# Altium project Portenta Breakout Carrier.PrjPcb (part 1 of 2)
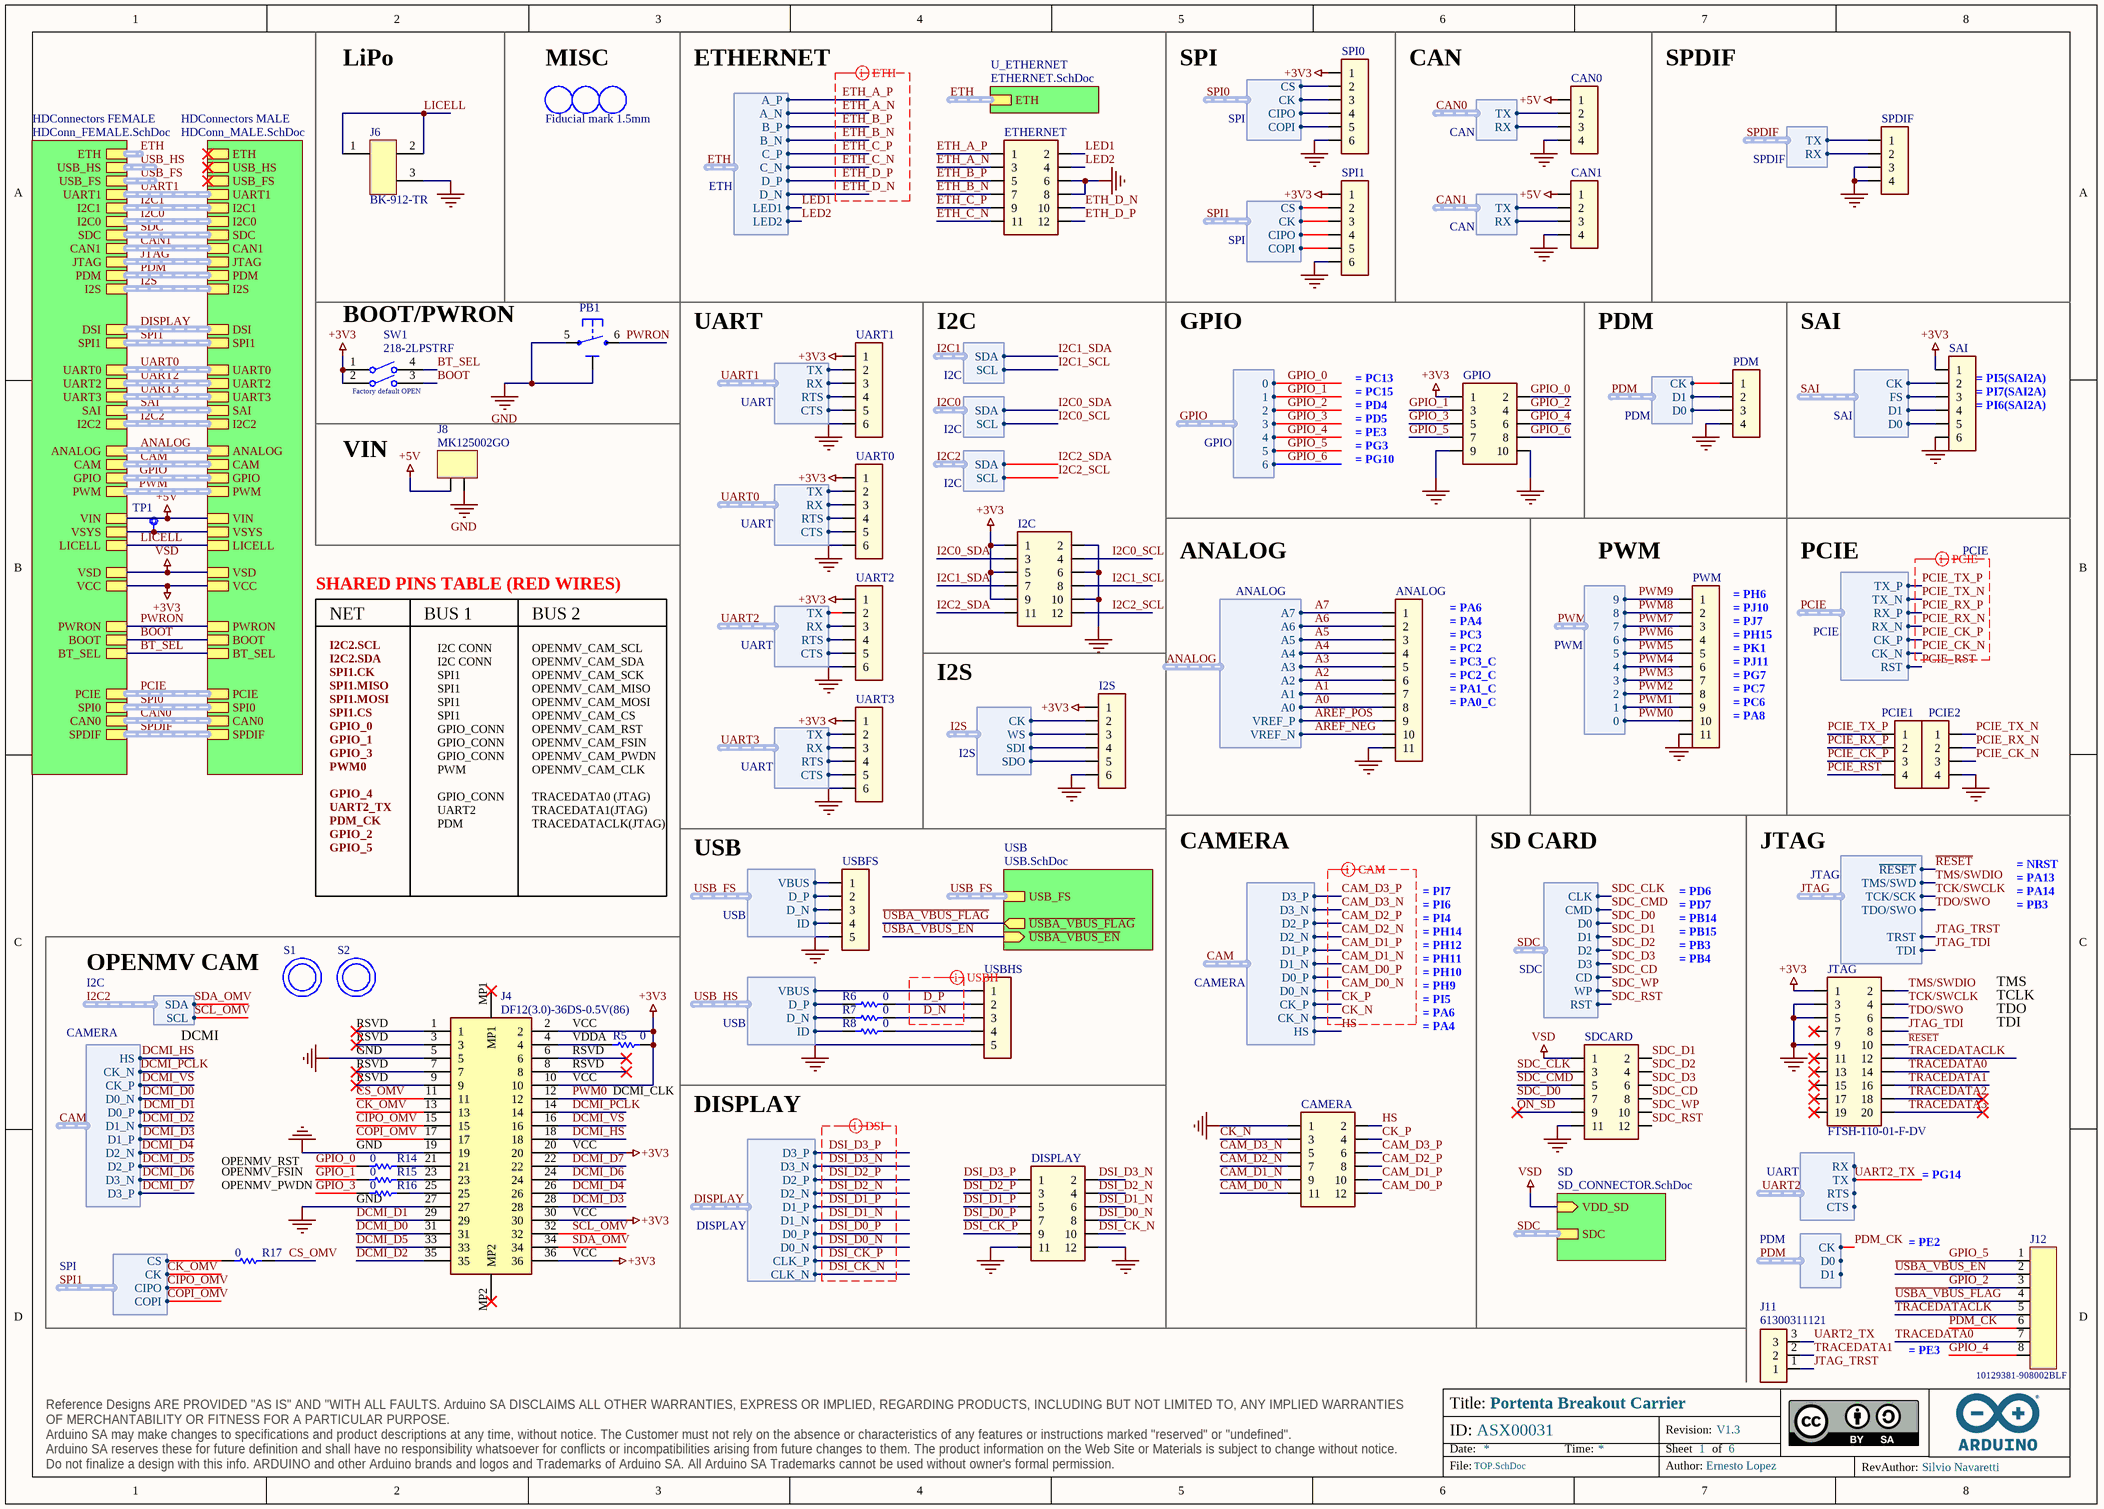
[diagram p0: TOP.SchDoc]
THICKNESS: 1.6mm; THD: X; TBD: _; TABS: _; SOLDERMASK_TOP: X; SOLDERMASK_PEELABLE_TOP: _; SOLDERMASK_PEELABLE_COLOR: _; SOLDERMASK_PEELABLE_BOTTOM: _; SOLDERMASK_COLOR: BLACK; SOLDERMASK_BOTTOM: X; SN/PB: _; SMD: X; SKU: ASX00031; SILK_TOP: X; SILK_COLOR: WHITE; SILK_BOTTOM: _; SCORING: X; RIGID/FLEX: _; RIGID: X; Revision: V1.3; PRESSFIT: _; POLYMIDE: _; PCB_SIZE: 164.00 mm x 72.00 mm; PANEL_SIZE: 184.00 mm x 165.00 mm; PANEL_REQUESTED: _; PANEL_PROVIDED: X; PANEL_NO: _; N_FIGURES: 2; NLAYERS: 4; NI/AU: _; MIN_TRACK_WIDTH_OUTER: 0.15mm; MIN_TRACK_WIDTH_INNER: 0.15mm; MIN_INSULATION_OUTER: 0.15mm; MIN_INSULATION_INNER: 0.15mm; MILLING: X; IPCNA: X; IPC3: _; IPC2: _; IPC1: _; HOLE_TOP_BOTTOM: X; HAL_LF: _; HAL: _; FR4_HTG: _; FR4: X; FLEX: _; FINISH_TBD: _; ENIG: X; EDGE_PLATING: _; DRILLS_SOLDER_FILLING: X; DRILLS_SLOT: _; DRILLS_RESIN_FILLING: _; DRILLS_PRESSFIT: _; DRILLS_LASER: _; DRILLS_FULL: X; DRILLS_COPPER_FILLING: _; DRILLS_BURIED: _; DRILLS_BLIND: _; BGA: _; Author: Ernesto Lopez; ADJUSTMENTS: _
6 sheets, 71 parts. Net scope: hierarchical (ports join the sheet entries above them; power ports are global).
Board files: Portenta_Brkout_Carrier.PcbDoc, Portenta_Carrier_Panel.PcbDoc
Sheets:
  TOP.SchDoc
    HDConnectors FEMALE = HDConn_FEMALE.SchDoc
    U_ETHERNET = ETHERNET.SchDoc
    USB = USB.SchDoc
    SD = SD_CONNECTOR.SchDoc
    HDConnectors MALE = HDConn_MALE.SchDoc

## Sheet TOP.SchDoc: Portenta Breakout Carrier
size A3; Author: Ernesto Lopez; DocumentNumber: ASX00031; Revision: V1.3; SheetNumber: 1; SheetTotal: 6; RevAuthor: Silvio Navaretti

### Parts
ANALOG  PIN HEADER 2.54mm VERT. 1x11POS  [PIN HEADER 2.54mm VERT. 1x11POS]  (value not drawn)
CAMERA  PIN HEADER 2.54mm VERT. 2x6POS  [PIN HEADER 2.54mm VERT. 2x6POS]  (value not drawn)
CAN0  PIN HEADER 2.54mm VERT. 1x4POS  [PIN HEADER 2.54mm VERT. 1x4POS-Footprint-1]  (value not drawn)
CAN1  PIN HEADER 2.54mm VERT. 1x4POS  [PIN HEADER 2.54mm VERT. 1x4POS-Footprint-1]  (value not drawn)
DISPLAY  PIN HEADER 2.54mm VERT. 2x6POS  [PIN HEADER 2.54mm VERT. 2x6POS]  (value not drawn)
ETHERNET  PIN HEADER 2.54mm VERT. 2x6POS  [PIN HEADER 2.54mm VERT. 2x6POS]  (value not drawn)
FD1  Fiducial mark 1.5mm  [FIDUCIAL-1.5]  (no BOM)
FD2  Fiducial mark 1.5mm  [FIDUCIAL-1.5]  (value not drawn)  (no BOM)
FD3  Fiducial mark 1.5mm  [FIDUCIAL-1.5]  (value not drawn)  (no BOM)
GPIO  PIN HEADER 2.54mm VERT. 2x5POS  [PIN HEADER 2.54mm VERT. 2x5POS]  (value not drawn)
I2C  PIN HEADER 2.54mm VERT. 2x6POS  [PIN HEADER 2.54mm VERT. 2x6POS]  (value not drawn)
I2S  PIN HEADER 2.54mm VERT. 1x6POS  [PIN HEADER 2.54mm VERT. 1x6POS]  (value not drawn)
J4  DF12(3.0)-36DS-0.5V(86)  [DF12(3.0)-36DS-0.5V(86)-Footprint-1]
J6  BK-912-TR  [MPD-CN-DIN-3_V]
J8  MK125002GO  [MK125002GO]
J11  61300311121  [61300311121]
J12  10129381-908002BLF  [61300211121]
JTAG  FTSH-110-01-F-DV  [FTSH-105-01-F-DV-Footprint-1]
PB1  PTS820J25KSMTRLFS  [C&K_PTS820_NO_HOLES-1]  (value not drawn)
PCIE1  PIN HEADER 2.54mm VERT. 1x4POS  [PIN HEADER 2.54mm VERT. 1x4POS-Footprint-1]  (value not drawn)
PCIE2  PIN HEADER 2.54mm VERT. 1x4POS  [PIN HEADER 2.54mm VERT. 1x4POS-Footprint-1]  (value not drawn)
PDM  PIN HEADER 2.54mm VERT. 1x4POS  [PIN HEADER 2.54mm VERT. 1x4POS-Footprint-1]  (value not drawn)
PWM  PIN HEADER 2.54mm VERT. 1x11POS  [PIN HEADER 2.54mm VERT. 1x11POS]  (value not drawn)
R5  value 0  [RES-0402]  (hidden comment: CRCW04020000Z0EDC)
R6  value 0  [RES-0402]  (hidden comment: CRCW04020000Z0EDC)
R7  value 0  [RES-0402]  (hidden comment: CRCW04020000Z0EDC)
R8  value 0  [RES-0402]  (hidden comment: CRCW04020000Z0EDC)
R14  value 0  [RES-0402]  (hidden comment: CRCW04020000Z0EDC)
R15  value 0  [RES-0402]  (hidden comment: CRCW04020000Z0EDC)
R16  value 0  [RES-0402]  (hidden comment: CRCW04020000Z0EDC)
R17  value 0  [RES-0402]  (hidden comment: CRCW04020000Z0EDC)
S1  9774030243R  [9774030243R-Footprint-1]  (value not drawn)
S2  9774030243R  [9774030243R-Footprint-1]  (value not drawn)
SAI  PIN HEADER 2.54mm VERT. 1x6POS  [PIN HEADER 2.54mm VERT. 1x6POS]  (value not drawn)
SDCARD  PIN HEADER 2.54mm VERT. 2x6POS  [PIN HEADER 2.54mm VERT. 2x6POS]  (value not drawn)
SPDIF  PIN HEADER 2.54mm VERT. 1x4POS  [PIN HEADER 2.54mm VERT. 1x4POS-Footprint-1]  (value not drawn)
SPI0  PIN HEADER 2.54mm VERT. 1x6POS  [PIN HEADER 2.54mm VERT. 1x6POS]  (value not drawn)
SPI1  PIN HEADER 2.54mm VERT. 1x6POS  [PIN HEADER 2.54mm VERT. 1x6POS]  (value not drawn)
SW1  218-2LPSTRF  [CTS-218-2LPST_V]
TP1  CMP-018-0006-A.4  [TP-1.27MM]  (value not drawn)  (no BOM)
UART0  PIN HEADER 2.54mm VERT. 1x6POS  [PIN HEADER 2.54mm VERT. 1x6POS]  (value not drawn)
UART1  PIN HEADER 2.54mm VERT. 1x6POS  [PIN HEADER 2.54mm VERT. 1x6POS]  (value not drawn)
UART2  PIN HEADER 2.54mm VERT. 1x6POS  [PIN HEADER 2.54mm VERT. 1x6POS]  (value not drawn)
UART3  PIN HEADER 2.54mm VERT. 1x6POS  [PIN HEADER 2.54mm VERT. 1x6POS]  (value not drawn)
USBFS  PIN HEADER 2.54mm VERT. 1x5POS  [PIN HEADER 2.54mm VERT. 1x5POS]  (value not drawn)
USBHS  PIN HEADER 2.54mm VERT. 1x5POS  [PIN HEADER 2.54mm VERT. 1x5POS]  (value not drawn)

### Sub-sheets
HDConnectors FEMALE = HDConn_FEMALE.SchDoc: PWRON, BOOT, USB_HS (harness USB), UART0 (harness UART), SAI (harness SAI), I2C2 (harness I2C), USB_FS (harness USB), JTAG (harness JTAG), BT_SEL, I2S (harness I2S), I2C0 (harness I2C), ETH (harness ETH), PWM (harness PWM), I2C1 (harness I2C), GPIO (harness GPIO), SPI1 (harness SPI), VCC, UART3 (harness UART), CAM (harness CAMERA), LICELL, PDM (harness PDM), DSI (harness DISPLAY), CAN1 (harness CAN), SDC (harness SDC), UART2 (harness UART), ANALOG (harness ANALOG), UART1 (harness UART), VIN, VSYS, CAN0 (harness GPIO), SPI0 (harness GPIO), PCIE (harness GPIO), SPDIF (harness GPIO), VSD
HDConnectors MALE = HDConn_MALE.SchDoc: SPI1 (harness SPI), SAI (harness SAI), UART3 (harness UART), UART2 (harness UART), I2C2 (harness I2C), UART1 (harness UART), VSD, I2C0 (harness I2C), VIN, USB_HS (harness USB), PCIE (harness PCIE), I2C1 (harness I2C), CAM (harness CAMERA), VSYS, I2S (harness I2S), SPDIF (harness SPDIF), BOOT, CAN1 (harness CAN), ANALOG (harness ANALOG), PWRON, VCC, SPI0 (harness SPI), PWM (harness PWM), UART0 (harness UART), USB_FS (harness USB), SDC (harness SDC), PDM (harness PDM), ETH (harness ETH), DSI (harness DISPLAY), CAN0 (harness CAN), BT_SEL, LICELL, JTAG (harness JTAG), GPIO (harness GPIO)
SD = SD_CONNECTOR.SchDoc: SDC (harness SDC), VDD_SD (in)
U_ETHERNET = ETHERNET.SchDoc: ETH (harness ETH)
USB = USB.SchDoc: USB_FS (harness ETH), ~{USBA_VBUS_FLAG} (out), ~{USBA_VBUS_EN} (in)

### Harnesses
UART: RX, TX, RTS, CTS
I2C: SCL, SDA
I2S: CK, SDI, SDO, WS
USB: VBUS, D_P, D_N, ID
ETH: A_P, A_N, B_P, B_N, C_P, C_N, D_P, D_N, LED1, LED2
DISPLAY: CLK_N, CLK_P, D0_N, D0_P, D1_N, D1_P, D2_N, D2_P, D3_N, D3_P
CAN: RX, TX
SPI: CS, CK, CIPO, COPI
GPIO: 0, 1, 2, 3, 4, 5, 6
ANALOG: VREF_P, A0, A1, A2, A3, A7, A6, A5, A4, VREF_N
SDC: CLK, CMD, D0, D1, D2, D3, CD, WP, RST
PDM: CK, D0, D1
JTAG: ~{RESET}, TCK/SCK, TDI, TDO/SWO, TMS/SWD, TRST
SAI: CK, FS, D0, D1
PWM: 0, 1, 2, 3, 4, 5, 6, 7, 8, 9
PCIE: TX_P, TX_N, RX_P, RX_N, CK_P, CK_N, RST
SPDIF: RX, TX
CAMERA: D3_P, D3_N, D2_P, D2_N, D1_P, D1_N, D0_P, D0_N, CK_P, CK_N, HS
I2C: SDA, SCL

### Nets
+3V3: GPIO.1 I2C.1 I2C.5 I2C.9 I2S.1 J4.2 J4.10 J4.20 J4.30 J4.36 JTAG.1 R5.1 SAI.1 SPI0.1 SPI1.1 SW1.1 SW1.2 UART0.1 UART1.1 UART2.1 UART3.1 ; sheet HDConnectors FEMALE/VCC, sheet HDConnectors MALE/VCC
+5V: CAN0.1 CAN1.1 J8.1 ; sheet HDConnectors FEMALE/VIN, sheet HDConnectors MALE/VIN
GND: ANALOG.11 CAMERA.1 CAN0.4 CAN1.4 DISPLAY.11 DISPLAY.12 ETHERNET.6 ETHERNET.8 GPIO.9 GPIO.10 I2C.2 I2C.6 I2C.10 I2S.6 J4.5 J4.19 J4.27 J6.3(NEGATIVE) J8.2 JTAG.3 JTAG.5 JTAG.9 PB1.5 PB1.PAD PCIE2.4 PDM.4 PWM.11 SAI.6 SDCARD.11 SPDIF.3 SPDIF.4 SPI0.6 SPI1.6 UART0.6 UART1.6 UART2.6 UART3.6 USBFS.5 USBHS.5
VSD: SDCARD.1 ; sheet HDConnectors FEMALE/VSD, sheet SD/VDD_SD, sheet HDConnectors MALE/VSD
A0: ANALOG.8 ; sheet HDConnectors FEMALE/ANALOG.A0
A1: ANALOG.7 ; sheet HDConnectors FEMALE/ANALOG.A1
A2: ANALOG.6 ; sheet HDConnectors FEMALE/ANALOG.A2
A3: ANALOG.5 ; sheet HDConnectors FEMALE/ANALOG.A3
A4: ANALOG.4 ; sheet HDConnectors FEMALE/ANALOG.A4
A5: ANALOG.3 ; sheet HDConnectors FEMALE/ANALOG.A5
A6: ANALOG.2 ; sheet HDConnectors FEMALE/ANALOG.A6
A7: ANALOG.1 ; sheet HDConnectors FEMALE/ANALOG.A7
AREF_NEG: ANALOG.10 ; sheet HDConnectors FEMALE/ANALOG.VREF_N  [project net ANALOG.VREF_N]
AREF_POS: ANALOG.9 ; sheet HDConnectors FEMALE/ANALOG.VREF_P  [project net ANALOG.VREF_P]
BOOT: SW1.3 ; sheet HDConnectors FEMALE/BOOT, sheet HDConnectors MALE/BOOT
BT_SEL: SW1.4 ; sheet HDConnectors FEMALE/BT_SEL, sheet HDConnectors MALE/BT_SEL
CAM_D0_N: CAMERA.11 J4.31 ; sheet HDConnectors FEMALE/CAM.D0_N  [also labelled DCMI_D0]  [project net CAM.D0_N]
CAM_D0_P: CAMERA.12 J4.29 ; sheet HDConnectors FEMALE/CAM.D0_P  [also labelled DCMI_D1]  [project net CAM.D0_P]
CAM_D1_N: CAMERA.9 J4.35 ; sheet HDConnectors FEMALE/CAM.D1_N  [also labelled DCMI_D2]  [project net CAM.D1_N]
CAM_D1_P: CAMERA.10 J4.28 ; sheet HDConnectors FEMALE/CAM.D1_P  [also labelled DCMI_D3]  [project net CAM.D1_P]
CAM_D2_N: CAMERA.7 J4.26 ; sheet HDConnectors FEMALE/CAM.D2_N  [also labelled DCMI_D4]  [project net CAM.D2_N]
CAM_D2_P: CAMERA.8 J4.33 ; sheet HDConnectors FEMALE/CAM.D2_P  [also labelled DCMI_D5]  [project net CAM.D2_P]
CAM_D3_N: CAMERA.5 J4.24 ; sheet HDConnectors FEMALE/CAM.D3_N  [also labelled DCMI_D6]  [project net CAM.D3_N]
CAM_D3_P: CAMERA.6 J4.22 ; sheet HDConnectors FEMALE/CAM.D3_P  [also labelled DCMI_D7]  [project net CAM.D3_P]
CAN0.RX: CAN0.3 ; sheet HDConnectors FEMALE/CAN0.RX
CAN0.TX: CAN0.2 ; sheet HDConnectors FEMALE/CAN0.TX
CAN1.RX: CAN1.3 ; sheet HDConnectors FEMALE/CAN1.RX
CAN1.TX: CAN1.2 ; sheet HDConnectors FEMALE/CAN1.TX
CIPO_OMV: J4.15 SPI1.4 ; sheet HDConnectors FEMALE/SPI1.CIPO
CK_N: CAMERA.3 J4.14 ; sheet HDConnectors FEMALE/CAM.CK_N  [also labelled DCMI_PCLK]  [project net CAM.CK_N]
CK_OMV: J4.13 SPI1.3 ; sheet HDConnectors FEMALE/SPI1.CK
CK_P: CAMERA.4 J4.16 ; sheet HDConnectors FEMALE/CAM.CK_P  [also labelled DCMI_VS]  [project net CAM.CK_P]
COPI_OMV: J4.17 SPI1.5 ; sheet HDConnectors FEMALE/SPI1.COPI
CS_OMV: J4.11 R17.1  [project net CS_OMV_1]
D_N: R7.1 USBHS.3  [project net D_N_1]
D_P: R6.1 USBHS.2  [project net D_P_1]
DCMI_HS: CAMERA.2 J4.18 ; sheet HDConnectors FEMALE/CAM.HS  [also labelled HS]  [project net CAM.HS]
DSI_CK_N: DISPLAY.10 ; sheet HDConnectors FEMALE/DSI.CLK_N  [project net DISPLAY.CLK_N]
DSI_CK_P: DISPLAY.9 ; sheet HDConnectors FEMALE/DSI.CLK_P  [project net DISPLAY.CLK_P]
DSI_D0_N: DISPLAY.8 ; sheet HDConnectors FEMALE/DSI.D0_N  [project net DISPLAY.D0_N]
DSI_D0_P: DISPLAY.7 ; sheet HDConnectors FEMALE/DSI.D0_P  [project net DISPLAY.D0_P]
DSI_D1_N: DISPLAY.6 ; sheet HDConnectors FEMALE/DSI.D1_N  [project net DISPLAY.D1_N]
DSI_D1_P: DISPLAY.5 ; sheet HDConnectors FEMALE/DSI.D1_P  [project net DISPLAY.D1_P]
DSI_D2_N: DISPLAY.4 ; sheet HDConnectors FEMALE/DSI.D2_N  [project net DISPLAY.D2_N]
DSI_D2_P: DISPLAY.3 ; sheet HDConnectors FEMALE/DSI.D2_P  [project net DISPLAY.D2_P]
DSI_D3_N: DISPLAY.2 ; sheet HDConnectors FEMALE/DSI.D3_N  [project net DISPLAY.D3_N]
DSI_D3_P: DISPLAY.1 ; sheet HDConnectors FEMALE/DSI.D3_P  [project net DISPLAY.D3_P]
ETH_A_N: ETHERNET.3 ; sheet HDConnectors FEMALE/ETH.A_N  [project net ETH.A_N]
ETH_A_P: ETHERNET.1 ; sheet HDConnectors FEMALE/ETH.A_P  [project net ETH.A_P]
ETH_B_N: ETHERNET.7 ; sheet HDConnectors FEMALE/ETH.B_N  [project net ETH.B_N]
ETH_B_P: ETHERNET.5 ; sheet HDConnectors FEMALE/ETH.B_P  [project net ETH.B_P]
ETH_C_N: ETHERNET.11 ; sheet HDConnectors FEMALE/ETH.C_N  [project net ETH.C_N]
ETH_C_P: ETHERNET.9 ; sheet HDConnectors FEMALE/ETH.C_P  [project net ETH.C_P]
ETH_D_N: ETHERNET.10 ; sheet HDConnectors FEMALE/ETH.D_N  [project net ETH.D_N]
ETH_D_P: ETHERNET.12 ; sheet HDConnectors FEMALE/ETH.D_P  [project net ETH.D_P]
GPIO_0: GPIO.2 R14.2 ; sheet HDConnectors FEMALE/GPIO.0  [project net GPIO.0]
GPIO_1: GPIO.3 R15.2 ; sheet HDConnectors FEMALE/GPIO.1  [project net GPIO.1]
GPIO_2: GPIO.4 J12.3 ; sheet HDConnectors FEMALE/GPIO.2  [project net GPIO.2]
GPIO_3: GPIO.5 R16.2 ; sheet HDConnectors FEMALE/GPIO.3  [project net GPIO.3]
GPIO_4: GPIO.6 J12.8 ; sheet HDConnectors FEMALE/GPIO.4  [project net GPIO.4]
GPIO_5: GPIO.7 J12.1 ; sheet HDConnectors FEMALE/GPIO.5  [project net GPIO.5]
GPIO_6: GPIO.8 ; sheet HDConnectors FEMALE/GPIO.6  [project net GPIO.6]
I2C0_SCL: I2C.4 ; sheet HDConnectors FEMALE/I2C0.SCL  [project net I2C0.SCL]
I2C0_SDA: I2C.3 ; sheet HDConnectors FEMALE/I2C0.SDA  [project net I2C0.SDA]
I2C1_SCL: I2C.8 ; sheet HDConnectors FEMALE/I2C1.SCL  [project net I2C1.SCL]
I2C1_SDA: I2C.7 ; sheet HDConnectors FEMALE/I2C1.SDA  [project net I2C1.SDA]
I2C2_SCL: I2C.12 J4.32 ; sheet HDConnectors FEMALE/I2C2.SCL  [also labelled SCL_OMV]  [project net I2C2.SCL]
I2C2_SDA: I2C.11 J4.34 ; sheet HDConnectors FEMALE/I2C2.SDA  [also labelled SDA_OMV]  [project net I2C2.SDA]
I2S.CK: I2S.2 ; sheet HDConnectors FEMALE/I2S.CK
I2S.SDI: I2S.4 ; sheet HDConnectors FEMALE/I2S.SDI
I2S.SDO: I2S.5 ; sheet HDConnectors FEMALE/I2S.SDO
I2S.WS: I2S.3 ; sheet HDConnectors FEMALE/I2S.WS
JTAG_TDI: JTAG.8 ; sheet HDConnectors FEMALE/JTAG.TDI  [project net JTAG.TDI]
JTAG_TRST: J11.1 ; sheet HDConnectors FEMALE/JTAG.TRST  [project net JTAG.TRST]
LED1: ETHERNET.2 ; sheet HDConnectors FEMALE/ETH.LED1  [project net ETH.LED1]
LED2: ETHERNET.4 ; sheet HDConnectors FEMALE/ETH.LED2  [project net ETH.LED2]
LICELL: J6.1(POSITIVE) J6.2(POSITIVE) ; sheet HDConnectors FEMALE/LICELL, sheet HDConnectors MALE/LICELL
ON_SD: SDCARD.9  [project net ON_SD_1]
PCIE_CK_N: PCIE2.3 ; sheet HDConnectors FEMALE/PCIE.CK_N  [project net PCIE.CK_N]
PCIE_CK_P: PCIE1.3 ; sheet HDConnectors FEMALE/PCIE.CK_P  [project net PCIE.CK_P]
PCIE_RST: PCIE1.4 ; sheet HDConnectors FEMALE/PCIE.RST  [project net PCIE.RST]
PCIE_RX_N: PCIE2.2 ; sheet HDConnectors FEMALE/PCIE.RX_N  [project net PCIE.RX_N]
PCIE_RX_P: PCIE1.2 ; sheet HDConnectors FEMALE/PCIE.RX_P  [project net PCIE.RX_P]
PCIE_TX_N: PCIE2.1 ; sheet HDConnectors FEMALE/PCIE.TX_N  [project net PCIE.TX_N]
PCIE_TX_P: PCIE1.1 ; sheet HDConnectors FEMALE/PCIE.TX_P  [project net PCIE.TX_P]
PDM.D0: PDM.3 ; sheet HDConnectors FEMALE/PDM.D0
PDM.D1: PDM.2 ; sheet HDConnectors FEMALE/PDM.D1
PDM_CK: J12.6 PDM.1 ; sheet HDConnectors FEMALE/PDM.CK  [project net PDM.CK]
PWM0: J4.12 PWM.10 ; sheet HDConnectors FEMALE/PWM.0  [project net PWM.0]
PWM1: PWM.9 ; sheet HDConnectors FEMALE/PWM.1  [project net PWM.1]
PWM2: PWM.8 ; sheet HDConnectors FEMALE/PWM.2  [project net PWM.2]
PWM3: PWM.7 ; sheet HDConnectors FEMALE/PWM.3  [project net PWM.3]
PWM4: PWM.6 ; sheet HDConnectors FEMALE/PWM.4  [project net PWM.4]
PWM5: PWM.5 ; sheet HDConnectors FEMALE/PWM.5  [project net PWM.5]
PWM6: PWM.4 ; sheet HDConnectors FEMALE/PWM.6  [project net PWM.6]
PWM7: PWM.3 ; sheet HDConnectors FEMALE/PWM.7  [project net PWM.7]
PWM8: PWM.2 ; sheet HDConnectors FEMALE/PWM.8  [project net PWM.8]
PWM9: PWM.1 ; sheet HDConnectors FEMALE/PWM.9  [project net PWM.9]
PWRON: PB1.6 ; sheet HDConnectors FEMALE/PWRON, sheet HDConnectors MALE/PWRON
~{RESET}: JTAG.10 ; sheet HDConnectors FEMALE/JTAG.~{RESET}  [project net JTAG.~{RESET}]
SAI.CK: SAI.2 ; sheet HDConnectors FEMALE/SAI.CK
SAI.D0: SAI.5 ; sheet HDConnectors FEMALE/SAI.D0
SAI.D1: SAI.4 ; sheet HDConnectors FEMALE/SAI.D1
SAI.FS: SAI.3 ; sheet HDConnectors FEMALE/SAI.FS
SDC_CD: SDCARD.8 ; sheet HDConnectors FEMALE/SDC.CD  [project net SDC.CD]
SDC_CLK: SDCARD.3 ; sheet HDConnectors FEMALE/SDC.CLK  [project net SDC.CLK]
SDC_CMD: SDCARD.5 ; sheet HDConnectors FEMALE/SDC.CMD  [project net SDC.CMD]
SDC_D0: SDCARD.7 ; sheet HDConnectors FEMALE/SDC.D0  [project net SDC.D0]
SDC_D1: SDCARD.2 ; sheet HDConnectors FEMALE/SDC.D1  [project net SDC.D1]
SDC_D2: SDCARD.4 ; sheet HDConnectors FEMALE/SDC.D2  [project net SDC.D2]
SDC_D3: SDCARD.6 ; sheet HDConnectors FEMALE/SDC.D3  [project net SDC.D3]
SDC_RST: SDCARD.12 ; sheet HDConnectors FEMALE/SDC.RST  [project net SDC.RST]
SDC_WP: SDCARD.10 ; sheet HDConnectors FEMALE/SDC.WP  [project net SDC.WP]
SPDIF.RX: SPDIF.2 ; sheet HDConnectors FEMALE/SPDIF.RX
SPDIF.TX: SPDIF.1 ; sheet HDConnectors FEMALE/SPDIF.TX
SPI0.CIPO: SPI0.4 ; sheet HDConnectors FEMALE/SPI0.CIPO
SPI0.CK: SPI0.3 ; sheet HDConnectors FEMALE/SPI0.CK
SPI0.COPI: SPI0.5 ; sheet HDConnectors FEMALE/SPI0.COPI
SPI0.CS: SPI0.2 ; sheet HDConnectors FEMALE/SPI0.CS
SPI1.CS: R17.2 SPI1.2 ; sheet HDConnectors FEMALE/SPI1.CS
TCK/SWCLK: JTAG.4 ; sheet HDConnectors FEMALE/JTAG.TCK/SCK  [project net JTAG.TCK/SCK]
TDO/SWO: JTAG.6 ; sheet HDConnectors FEMALE/JTAG.TDO/SWO  [project net JTAG.TDO/SWO]
TMS/SWDIO: JTAG.2 ; sheet HDConnectors FEMALE/JTAG.TMS/SWD  [project net JTAG.TMS/SWD]
TRACEDATA0: J12.7 JTAG.14  [project net TRACEDATA0_1]
TRACEDATA1: J11.2 JTAG.16  [project net TRACEDATA1_1]
TRACEDATA2: JTAG.18  [project net TRACEDATA2_1]
TRACEDATA3: JTAG.20  [project net TRACEDATA3_1]
TRACEDATACLK: J12.5 JTAG.12  [project net TRACEDATACLK_1]
~{USBA_VBUS_EN}: J12.2 ; sheet USB/~{USBA_VBUS_EN}
~{USBA_VBUS_FLAG}: J12.4 ; sheet USB/~{USBA_VBUS_FLAG}
UART0.CTS: UART0.5 ; sheet HDConnectors FEMALE/UART0.CTS
UART0.RTS: UART0.4 ; sheet HDConnectors FEMALE/UART0.RTS
UART0.RX: UART0.3 ; sheet HDConnectors FEMALE/UART0.RX
UART0.TX: UART0.2 ; sheet HDConnectors FEMALE/UART0.TX
UART1.CTS: UART1.5 ; sheet HDConnectors FEMALE/UART1.CTS
UART1.RTS: UART1.4 ; sheet HDConnectors FEMALE/UART1.RTS
UART1.RX: UART1.3 ; sheet HDConnectors FEMALE/UART1.RX
UART1.TX: UART1.2 ; sheet HDConnectors FEMALE/UART1.TX
UART2.CTS: UART2.5 ; sheet HDConnectors FEMALE/UART2.CTS
UART2.RTS: UART2.4 ; sheet HDConnectors FEMALE/UART2.RTS
UART2.RX: UART2.3 ; sheet HDConnectors FEMALE/UART2.RX
UART2_TX: J11.3 UART2.2 ; sheet HDConnectors FEMALE/UART2.TX  [project net UART2.TX]
UART3.CTS: UART3.5 ; sheet HDConnectors FEMALE/UART3.CTS
UART3.RTS: UART3.4 ; sheet HDConnectors FEMALE/UART3.RTS
UART3.RX: UART3.3 ; sheet HDConnectors FEMALE/UART3.RX
UART3.TX: UART3.2 ; sheet HDConnectors FEMALE/UART3.TX
USB_FS.D_N: USBFS.3 ; sheet HDConnectors FEMALE/USB_FS.D_N
USB_FS.D_P: USBFS.2 ; sheet HDConnectors FEMALE/USB_FS.D_P
USB_FS.ID: USBFS.4 ; sheet HDConnectors FEMALE/USB_FS.ID
USB_FS.VBUS: USBFS.1 ; sheet HDConnectors FEMALE/USB_FS.VBUS
USB_HS.D_N: R7.2 ; sheet HDConnectors FEMALE/USB_HS.D_N
USB_HS.D_P: R6.2 ; sheet HDConnectors FEMALE/USB_HS.D_P
USB_HS.ID: R8.2 ; sheet HDConnectors FEMALE/USB_HS.ID
USB_HS.VBUS: USBHS.1 ; sheet HDConnectors FEMALE/USB_HS.VBUS
VSYS: TP1.X ; sheet HDConnectors FEMALE/VSYS, sheet HDConnectors MALE/VSYS
NetJ4_4: J4.4 R5.2
NetJ4_21: J4.21 R14.1
NetJ4_23: J4.23 R15.1
NetJ4_25: J4.25 R16.1
NetR8_1: R8.1 USBHS.4

Not connected (* = marked no-connect by the designer): J4 1* 3* 6* 7* 8* 9* MP1* MP2*; JTAG 7* 11* 13* 15* 17* 19*

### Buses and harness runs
harness ANALOG = sheet HDConnectors FEMALE/ANALOG = sheet HDConnectors MALE/ANALOG
harness CAM = sheet HDConnectors FEMALE/CAM = sheet HDConnectors MALE/CAM
harness CAN0 = sheet HDConnectors FEMALE/CAN0 = sheet HDConnectors MALE/CAN0
harness CAN1 = sheet HDConnectors FEMALE/CAN1 = sheet HDConnectors MALE/CAN1
harness DISPLAY = sheet HDConnectors FEMALE/DSI = sheet HDConnectors MALE/DSI
harness ETH = sheet HDConnectors FEMALE/ETH
harness ETH = sheet U_ETHERNET/ETH
harness GPIO = sheet HDConnectors FEMALE/GPIO = sheet HDConnectors MALE/GPIO
harness I2C0 = sheet HDConnectors FEMALE/I2C0 = sheet HDConnectors MALE/I2C0
harness I2C1 = sheet HDConnectors FEMALE/I2C1 = sheet HDConnectors MALE/I2C1
harness I2C2 = sheet HDConnectors FEMALE/I2C2 = sheet HDConnectors MALE/I2C2
harness I2S = sheet HDConnectors FEMALE/I2S = sheet HDConnectors MALE/I2S
harness JTAG = sheet HDConnectors FEMALE/JTAG = sheet HDConnectors MALE/JTAG
harness PCIE = sheet HDConnectors FEMALE/PCIE = sheet HDConnectors MALE/PCIE
harness PDM = sheet HDConnectors FEMALE/PDM = sheet HDConnectors MALE/PDM
harness PWM = sheet HDConnectors FEMALE/PWM = sheet HDConnectors MALE/PWM
harness SAI = sheet HDConnectors FEMALE/SAI = sheet HDConnectors MALE/SAI
harness SDC = sheet HDConnectors FEMALE/SDC = sheet HDConnectors MALE/SDC
harness SDC = sheet SD/SDC
harness SPDIF = sheet HDConnectors FEMALE/SPDIF = sheet HDConnectors MALE/SPDIF
harness SPI0 = sheet HDConnectors FEMALE/SPI0 = sheet HDConnectors MALE/SPI0
harness SPI1 = sheet HDConnectors FEMALE/SPI1 = sheet HDConnectors MALE/SPI1
harness UART0 = sheet HDConnectors FEMALE/UART0 = sheet HDConnectors MALE/UART0
harness UART1 = sheet HDConnectors FEMALE/UART1 = sheet HDConnectors MALE/UART1
harness UART2 = sheet HDConnectors FEMALE/UART2 = sheet HDConnectors MALE/UART2
harness UART3 = sheet HDConnectors FEMALE/UART3 = sheet HDConnectors MALE/UART3
harness USB_FS = sheet HDConnectors FEMALE/USB_FS
harness USB_FS = sheet USB/USB_FS
harness USB_HS = sheet HDConnectors FEMALE/USB_HS

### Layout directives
differential pair; differential pair class ETH: ETH_A_N, ETH_A_P, ETH_B_N, ETH_B_P, ETH_C_N, ETH_C_P, ETH_D_N, ETH_D_P
differential pair; differential pair class DSI: DSI_CK_N, DSI_CK_P, DSI_D0_N, DSI_D0_P, DSI_D1_N, DSI_D1_P, DSI_D2_N, DSI_D2_P, DSI_D3_N, DSI_D3_P
differential pair; differential pair class PCIE: PCIE_CK_N, PCIE_CK_P, PCIE_RX_N, PCIE_RX_P, PCIE_TX_N, PCIE_TX_P
differential pair; differential pair class USB; net class USB: D_N, D_P
differential pair; differential pair class CAM: CAM_D0_N, CAM_D0_P, CAM_D1_N, CAM_D1_P, CAM_D2_N, CAM_D2_P, CAM_D3_N, CAM_D3_P, CK_N, CK_P

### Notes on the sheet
- LiPo
- MISC
- ETHERNET
- SPI
- CAN
- SPDIF
- (near SW1) BOOT/PWRON
- UART
- I2C
- GPIO
- PDM
- SAI
- VIN
- ANALOG
- PWM
- PCIE
- SHARED PINS TABLE (RED WIRES)
- NET
- BUS 1
- I2C CONN
- OPENMV_CAM_SCL
- BUS 2
- SPI1
- OPENMV_CAM_SDA
- OPENMV_CAM_SCK
- OPENMV_CAM_MISO
- OPENMV_CAM_MOSI
- OPENMV_CAM_CS
- I2S
- GPIO_CONN
- OPENMV_CAM_CLK
- OPENMV_CAM_RST
- OPENMV_CAM_FSIN
- OPENMV_CAM_PWDN
- UART2
- TRACEDATA0 (JTAG)
- TRACEDATA1(JTAG)
- TRACEDATACLK(JTAG)
- USB
- CAMERA
- SD CARD
- (near PWM) Harness and connector mismatch
- JTAG
- 0 ohm resistor jumpers?
- USB HS: Solder jumpers Normally open.
  USB FS: uUSB connector + headers
- OPENMV CAM
- TMS
- DCMI
- (near S2) RSVD
- RSVD
- GND
- (near R5) VDDA
- VCC
- (near R5) RSVD
- TCLK
- TDO
- TDI
- (near R5) DCMI_CLK
- DISPLAY
- OPENMV_PWDN
- OPENMV_FSIN
- OPENMV_RST
- (near R14) GND
- (near J4) VCC
- (near R16) GND
- Labels drawn without touching a wire or pin: GPIO_0, GPIO_1, GPIO_2, GPIO_3, GPIO_4, GPIO_5, I2C2.SCL, I2C2.SDA, PDM_CK, PWM0, SPI1.CK, SPI1.CS, SPI1.MISO, SPI1.MOSI, UART2_TX

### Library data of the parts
ANALOG PWM = J0170-A.1: Code Arduino: J0170
CAMERA DISPLAY ETHERNET I2C SDCARD = J0165-A.1: Code Arduino: J0165
CAN0 = J0162-A.3: Code Arduino: J0162
CAN1 PCIE1 PCIE2 PDM SPDIF = J0162-A.2: Code Arduino: J0162
FD1-FD3 = UT0000-A.3
GPIO = J0166-A.1: Code Arduino: J0166
I2S SAI SPI0 SPI1 UART0-UART3 = J0167-A.1: Code Arduino: J0167
J4 = J0177-A.2: CONN RCPT 36POS SMD GOLD H3.0mm; Manufacturer: Hirose; Mating Contact Pitch: 0.02inch; PCB Contact Row Spacing: 3.6068mm; Number of Contacts: 36; Durability: 50Cycles; Mounting Option 1: LOCKING; Contact Pattern: RECTANGULAR; Number of Rows Loaded: 2; DIN Conformance: No; Dielectric Withstanding Voltage (AC): 150V; Reference Standard: UL; Reliability: COMMERCIAL; Contact Resistance: 50mR; Connector Type: BOARD STACKING CONNECTOR; Code Arduino: J0177; Body/Shell Style: RECEPTACLE; Number Of Connectors: 1; Rated Current (Signal): 300mA; Insulation Resistance: 500MR; Mating Information: MULTIPLE MATING PARTS AVAILABLE; Option: General Purpose
J6 = J0072-A.3: BATTERY RETAINER COIN 20MM SMD; Manufacturer: Memory Protection Devices; Code Arduino: J0072
J8 = J0012-A.4: CONN MORS.CS 2v p3,5 10A aLING.VER; Manufacturer: Adimpex; Code Arduino: 2341
J11 = J0184-A.4: CONN HEADER VERT 3POS 2.54MM; Insulation Resistance: 1GR; Contact Resistance: 20mR; Connector Type: BOARD CONNECTOR; Code Arduino: J0184; Number of Contacts: 3
J12 = J0195-A.2: CONN HEADER VERT 2x4 8POS 2.54MM; Manufacturer: Wurth Electronics; Contact Resistance: 20mR; Number of Positions: 2; Pitch: 0.1inch; Number of Contacts: 8; Code Arduino: J0195; Voltage Rating: 250V; Current Rating: 3A; Insulation Resistance: 1GR; Connector Type: BOARD CONNECTOR; Gender: Male
JTAG = J0203-A.1: CONN HEADER SMD 20POS 2x10 1.27MM JTAG; Manufacturer: Samtec; Gender: Male; Number of Contacts: 20; Number of Positions: 10; Current Rating: 1.75A; Code Arduino: J0203; Connector Type: Male Pin; Row Spacing: 0.05inch
PB1 = B0006-A.6: PUSHBUTTON SMD PTS820 NO HOLES; Manufacturer: C&K; Code Arduino: A5506; Actuator Type: Standard; Mechanical Life: 100000Cycles
R5-R8 R14-R17 = R0000-A.5: RES CHIP 0402 0R 1/16W; Manufacturer: Vishay; Code Arduino: 0039; Power: 63mW; Tolerance: J
S1 S2 = S0013-A.1: ROUND STANDOFF M2X0.4 STEEL 3MM; Manufacturer: Würth Elektronik; Code Arduino: S0013
SW1 = S0006-A.5: Switch DIP normally open; Manufacturer: CTS Corporation; Code Arduino: S0006; Voltage Rating (DC): 24V; Throw Configuration: SPST; Number of Positions: 2; Actuator Type: Slide (Standard); Pitch: 0.05inch; Contact Resistance: 100mR; Electrical Life: 1000Cycles; Max Current Rating: 25mA; Washable: Yes
TP1 = UT0014-A.2: Test point 1.27mm
USBFS USBHS = J0163-A.2: Code Arduino: J0163

## Sheet HDConn_FEMALE.SchDoc: Portenta Breakout Carrier
size A3; Author: S. Navaretti; DocumentNumber: ASX00031; Revision: V1.3; SheetNumber: 2; SheetTotal: 6; RevAuthor: Silvio Navaretti
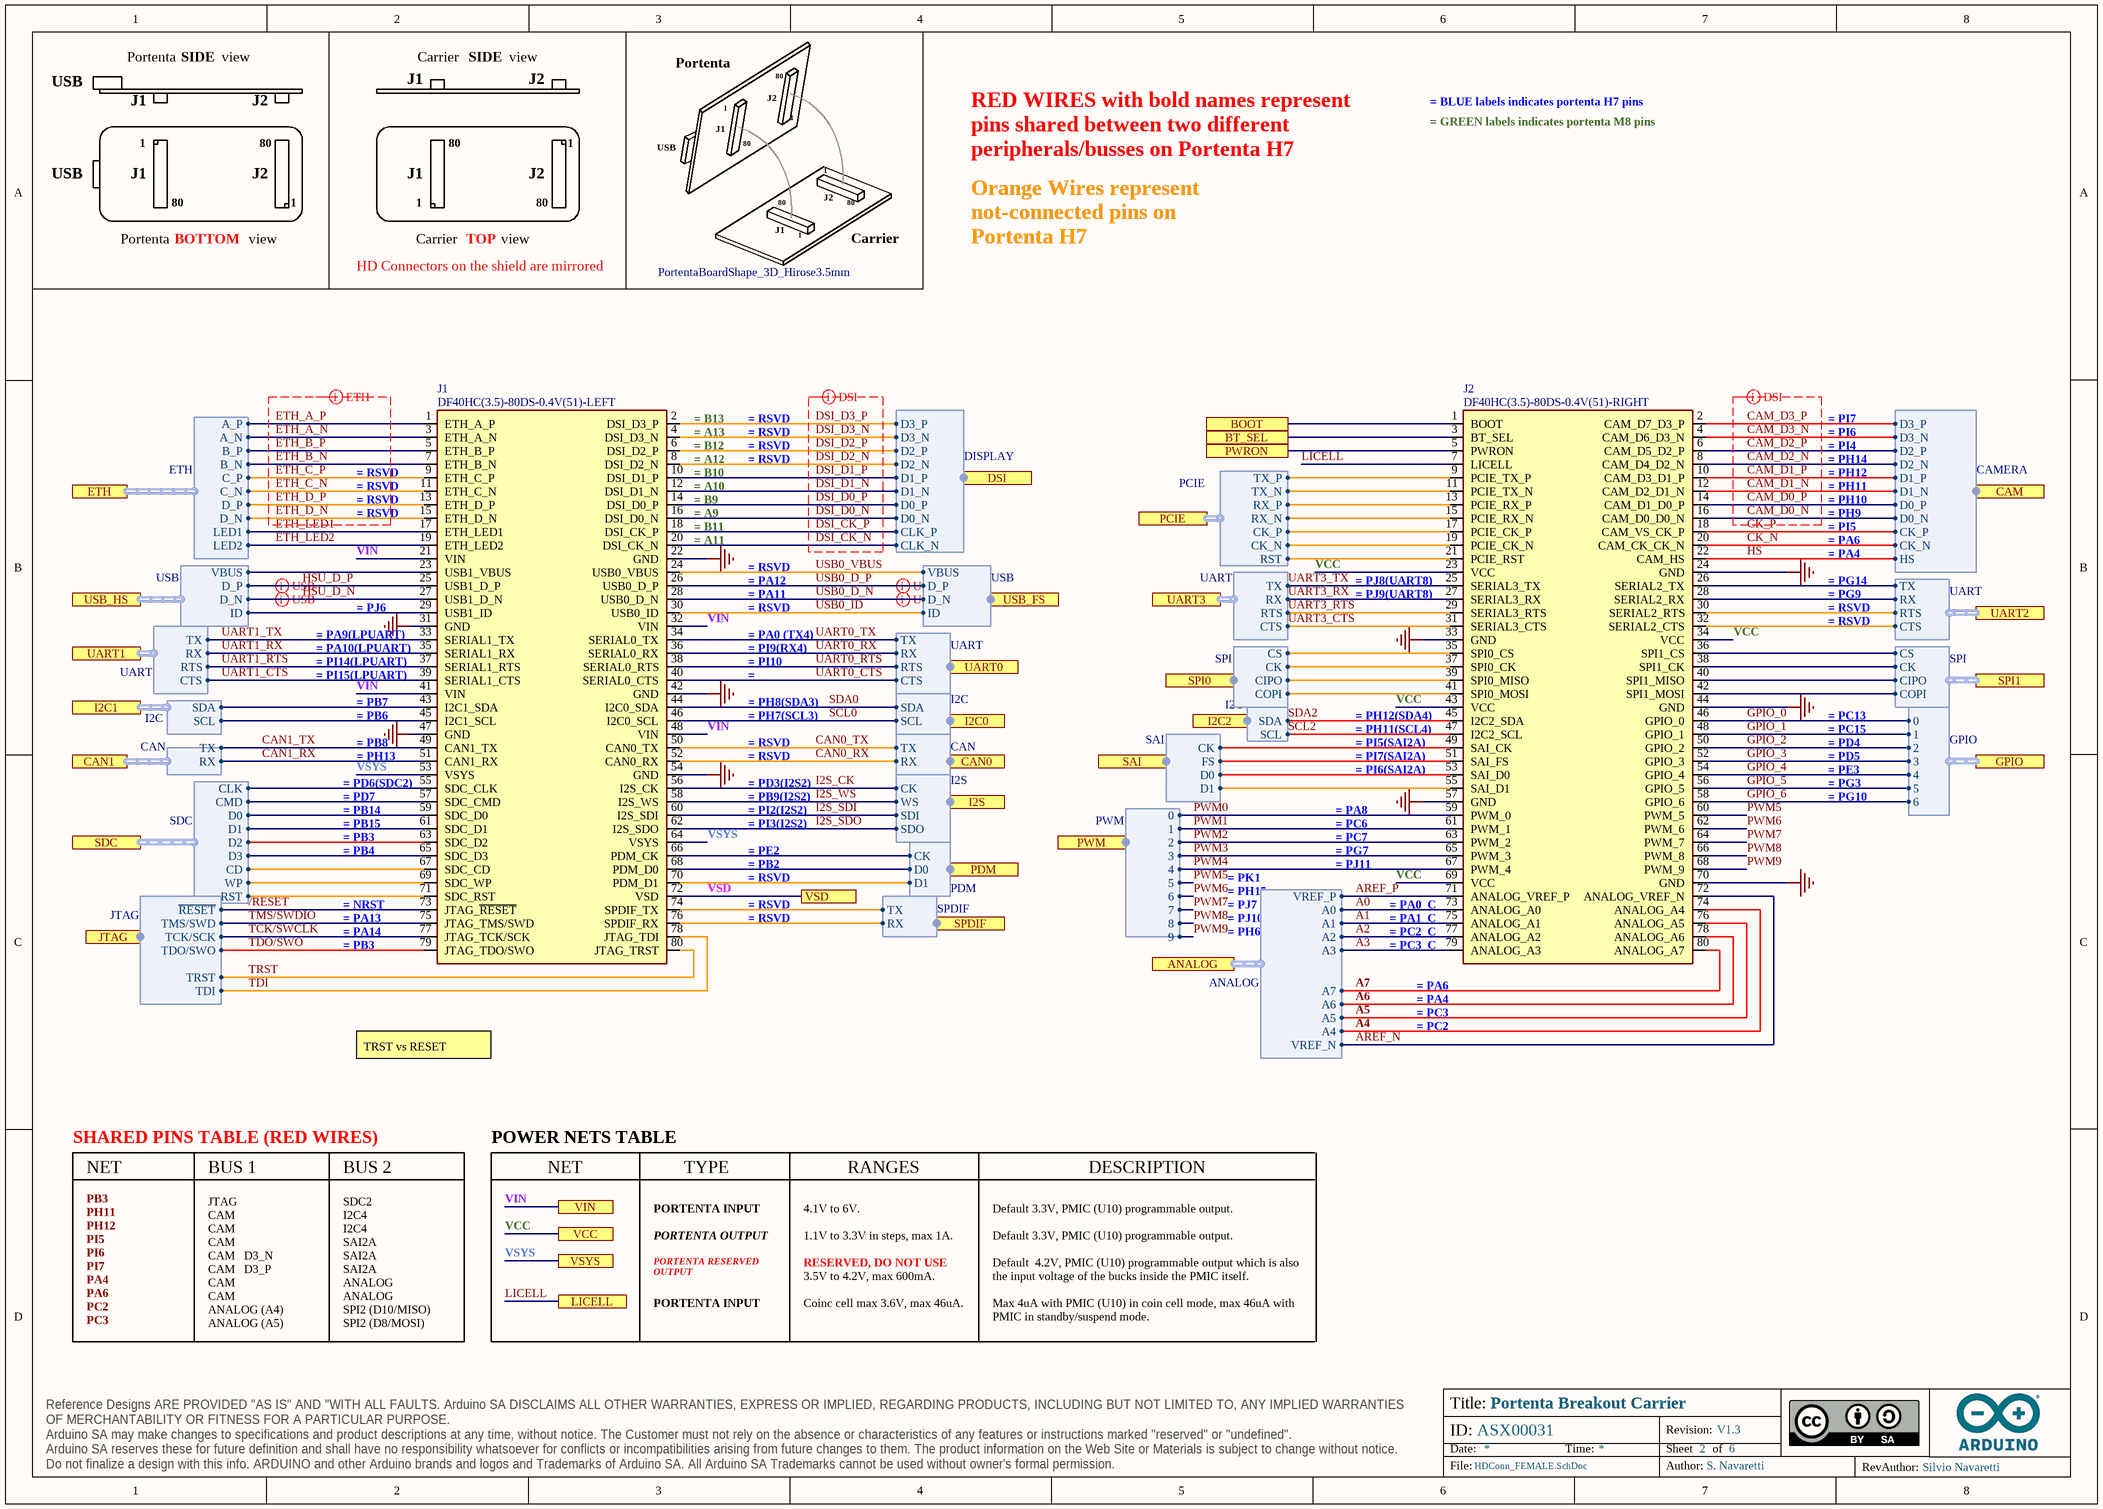
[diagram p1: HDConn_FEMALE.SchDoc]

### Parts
J1  DF40HC(3.5)-80DS-0.4V(51)-LEFT  [DF40HC(3.5)-80DS-0.4V(51)-Footprint-1]
J2  DF40HC(3.5)-80DS-0.4V(51)-RIGHT  [DF40HC(3.5)-80DS-0.4V(51)-Footprint-1]
PortentaBoardShape_3D_Hirose3.5mm  PortentaBoardShape_3D_Hirose3.5mm  [PortentaBoardShape3D-Footprint-1]  (no BOM)

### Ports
ANALOG (harness ANALOG), BOOT, BT_SEL, CAM (harness CAMERA), CAN0 (harness CAN), CAN1 (harness CAN), DSI (harness DISPLAY), ETH (harness ETH), GPIO (harness GPIO), I2C0 (harness I2C), I2C1 (harness I2C), I2C2 (harness I2C), I2S (harness I2S), JTAG (harness JTAG), LICELL, PCIE (harness PCIE), PDM (harness PDM), PWM (harness PWM), PWRON, SAI (harness SAI), SDC (harness SDC), SPDIF (harness SPDIF), SPI0 (harness SPI), SPI1 (harness SPI), UART0 (harness UART), UART1 (harness UART), UART2 (harness UART), UART3 (harness UART), USB_FS (harness USB), USB_HS (harness USB), VCC, VIN, VSD, VSYS

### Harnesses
ANALOG: VREF_P, A0, A1, A2, A3, A7, A6, A5, A4, VREF_N
PWM: 0, 1, 2, 3, 4, 5, 6, 7, 8, 9
GPIO: 0, 1, 2, 3, 4, 5, 6
ETH: A_P, A_N, B_P, B_N, C_P, C_N, D_P, D_N, LED1, LED2
USB: VBUS, D_P, D_N, ID
UART: RX, TX, RTS, CTS
I2C: SCL, SDA
CAN: RX, TX
SDC: CLK, CMD, D0, D1, D2, D3, CD, WP, RST
JTAG: ~{RESET}, TCK/SCK, TDI, TDO/SWO, TMS/SWD, TRST
DISPLAY: CLK_N, CLK_P, D0_N, D0_P, D1_N, D1_P, D2_N, D2_P, D3_N, D3_P
I2C: SDA, SCL
I2S: CK, SDI, SDO, WS
PDM: CK, D0, D1
SAI: CK, FS, D0, D1
CAMERA: D3_P, D3_N, D2_P, D2_N, D1_P, D1_N, D0_P, D0_N, CK_P, CK_N, HS
SPI: CS, CK, CIPO, COPI
PCIE: TX_P, TX_N, RX_P, RX_N, CK_P, CK_N, RST
SPDIF: RX, TX

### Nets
GND: J1.22(GND) J1.31(GND) J1.42(GND) J1.47(GND) J1.54(GND) J2.24(GND) J2.33(GND) J2.44(GND) J2.57(GND) J2.70(GND)
VCC: J2.23(VCC) J2.34(VCC) J2.43(VCC) J2.69(VCC) ; port VCC  [project net +3V3]
VIN: J1.21(VIN) J1.32(VIN) J1.41(VIN) J1.48(VIN) ; port VIN  [project net +5V]
VSD: J1.72(VSD) ; port VSD
/RESET: J1.73(JTAG_~{RESET}) ; port JTAG.~{RESET}  [project net JTAG.~{RESET}]
A0: J2.73(ANALOG_A0) ; port ANALOG.A0
A1: J2.75(ANALOG_A1) ; port ANALOG.A1
A2: J2.77(ANALOG_A2) ; port ANALOG.A2
A3: J2.79(ANALOG_A3) ; port ANALOG.A3
A4: J2.74(ANALOG_A4) ; port ANALOG.A4
A5: J2.76(ANALOG_A5) ; port ANALOG.A5
A6: J2.78(ANALOG_A6) ; port ANALOG.A6
A7: J2.80(ANALOG_A7) ; port ANALOG.A7
AREF_N: J2.72(ANALOG_VREF_N) ; port ANALOG.VREF_N  [project net ANALOG.VREF_N]
AREF_P: J2.71(ANALOG_VREF_P) ; port ANALOG.VREF_P  [project net ANALOG.VREF_P]
BOOT: J2.1(BOOT) ; port BOOT
BT_SEL: J2.3(BT_SEL) ; port BT_SEL
CAM_D0_N: J2.16(CAM_D0_D0_N) ; port CAM.D0_N  [project net CAM.D0_N]
CAM_D0_P: J2.14(CAM_D1_D0_P) ; port CAM.D0_P  [project net CAM.D0_P]
CAM_D1_N: J2.12(CAM_D2_D1_N) ; port CAM.D1_N  [project net CAM.D1_N]
CAM_D1_P: J2.10(CAM_D3_D1_P) ; port CAM.D1_P  [project net CAM.D1_P]
CAM_D2_N: J2.8(CAM_D4_D2_N) ; port CAM.D2_N  [project net CAM.D2_N]
CAM_D2_P: J2.6(CAM_D5_D2_P) ; port CAM.D2_P  [project net CAM.D2_P]
CAM_D3_N: J2.4(CAM_D6_D3_N) ; port CAM.D3_N  [project net CAM.D3_N]
CAM_D3_P: J2.2(CAM_D7_D3_P) ; port CAM.D3_P  [project net CAM.D3_P]
CAN0_RX: J1.52(CAN0_RX) ; port CAN0.RX  [project net CAN0.RX]
CAN0_TX: J1.50(CAN0_TX) ; port CAN0.TX  [project net CAN0.TX]
CAN1_RX: J1.51(CAN1_RX) ; port CAN1.RX  [project net CAN1.RX]
CAN1_TX: J1.49(CAN1_TX) ; port CAN1.TX  [project net CAN1.TX]
CIPO_OMV: J2.40(SPI1_MISO) ; port SPI1.CIPO
CK_N: J2.20(CAM_CK_CK_N) ; port CAM.CK_N  [project net CAM.CK_N]
CK_OMV: J2.38(SPI1_CK) ; port SPI1.CK
CK_P: J2.18(CAM_VS_CK_P) ; port CAM.CK_P  [project net CAM.CK_P]
COPI_OMV: J2.42(SPI1_MOSI) ; port SPI1.COPI
DSI_CK_N: J1.20(DSI_CK_N) ; port DSI.CLK_N  [project net DISPLAY.CLK_N]
DSI_CK_P: J1.18(DSI_CK_P) ; port DSI.CLK_P  [project net DISPLAY.CLK_P]
DSI_D0_N: J1.16(DSI_D0_N) ; port DSI.D0_N  [project net DISPLAY.D0_N]
DSI_D0_P: J1.14(DSI_D0_P) ; port DSI.D0_P  [project net DISPLAY.D0_P]
DSI_D1_N: J1.12(DSI_D1_N) ; port DSI.D1_N  [project net DISPLAY.D1_N]
DSI_D1_P: J1.10(DSI_D1_P) ; port DSI.D1_P  [project net DISPLAY.D1_P]
DSI_D2_N: J1.8(DSI_D2_N) ; port DSI.D2_N  [project net DISPLAY.D2_N]
DSI_D2_P: J1.6(DSI_D2_P) ; port DSI.D2_P  [project net DISPLAY.D2_P]
DSI_D3_N: J1.4(DSI_D3_N) ; port DSI.D3_N  [project net DISPLAY.D3_N]
DSI_D3_P: J1.2(DSI_D3_P) ; port DSI.D3_P  [project net DISPLAY.D3_P]
ETH_A_N: J1.3(ETH_A_N) ; port ETH.A_N  [project net ETH.A_N]
ETH_A_P: J1.1(ETH_A_P) ; port ETH.A_P  [project net ETH.A_P]
ETH_B_N: J1.7(ETH_B_N) ; port ETH.B_N  [project net ETH.B_N]
ETH_B_P: J1.5(ETH_B_P) ; port ETH.B_P  [project net ETH.B_P]
ETH_C_N: J1.11(ETH_C_N) ; port ETH.C_N  [project net ETH.C_N]
ETH_C_P: J1.9(ETH_C_P) ; port ETH.C_P  [project net ETH.C_P]
ETH_D_N: J1.15(ETH_D_N) ; port ETH.D_N  [project net ETH.D_N]
ETH_D_P: J1.13(ETH_D_P) ; port ETH.D_P  [project net ETH.D_P]
ETH_LED1: J1.17(ETH_LED1) ; port ETH.LED1  [project net ETH.LED1]
ETH_LED2: J1.19(ETH_LED2) ; port ETH.LED2  [project net ETH.LED2]
GPIO_0: J2.46(GPIO_0) ; port GPIO.0  [project net GPIO.0]
GPIO_1: J2.48(GPIO_1) ; port GPIO.1  [project net GPIO.1]
GPIO_2: J2.50(GPIO_2) ; port GPIO.2  [project net GPIO.2]
GPIO_3: J2.52(GPIO_3) ; port GPIO.3  [project net GPIO.3]
GPIO_4: J2.54(GPIO_4) ; port GPIO.4  [project net GPIO.4]
GPIO_5: J2.56(GPIO_5) ; port GPIO.5  [project net GPIO.5]
GPIO_6: J2.58(GPIO_6) ; port GPIO.6  [project net GPIO.6]
HS: J2.22(CAM_HS) ; port CAM.HS  [project net CAM.HS]
HSU_D_N: J1.27(USB1_D_N) ; port USB_HS.D_N  [project net USB_HS.D_N]
HSU_D_P: J1.25(USB1_D_P) ; port USB_HS.D_P  [project net USB_HS.D_P]
I2C1.SCL: J1.45(I2C1_SCL) ; port I2C1.SCL
I2C1.SDA: J1.43(I2C1_SDA) ; port I2C1.SDA
I2S_CK: J1.56(I2S_CK) ; port I2S.CK  [project net I2S.CK]
I2S_SDI: J1.60(I2S_SDI) ; port I2S.SDI  [project net I2S.SDI]
I2S_SDO: J1.62(I2S_SDO) ; port I2S.SDO  [project net I2S.SDO]
I2S_WS: J1.58(I2S_WS) ; port I2S.WS  [project net I2S.WS]
LICELL: J2.7(LICELL) ; port LICELL
PCIE.CK_N: J2.19(PCIE_CK_N) ; port PCIE.CK_N
PCIE.CK_P: J2.17(PCIE_CK_P) ; port PCIE.CK_P
PCIE.RST: J2.21(PCIE_RST) ; port PCIE.RST
PCIE.RX_N: J2.15(PCIE_RX_N) ; port PCIE.RX_N
PCIE.RX_P: J2.13(PCIE_RX_P) ; port PCIE.RX_P
PCIE.TX_N: J2.11(PCIE_TX_N) ; port PCIE.TX_N
PCIE.TX_P: J2.9(PCIE_TX_P) ; port PCIE.TX_P
PDM.CK: J1.66(PDM_CK) ; port PDM.CK
PDM.D0: J1.68(PDM_D0) ; port PDM.D0
PDM.D1: J1.70(PDM_D1) ; port PDM.D1
PWM0: J2.59(PWM_0) ; port PWM.0  [project net PWM.0]
PWM1: J2.61(PWM_1) ; port PWM.1  [project net PWM.1]
PWM2: J2.63(PWM_2) ; port PWM.2  [project net PWM.2]
PWM3: J2.65(PWM_3) ; port PWM.3  [project net PWM.3]
PWM4: J2.67(PWM_4) ; port PWM.4  [project net PWM.4]
PWM5: J2.60(PWM_5) ; port PWM.5  [project net PWM.5]
PWM6: J2.62(PWM_6) ; port PWM.6  [project net PWM.6]
PWM7: J2.64(PWM_7) ; port PWM.7  [project net PWM.7]
PWM8: J2.66(PWM_8) ; port PWM.8  [project net PWM.8]
PWM9: J2.68(PWM_9) ; port PWM.9  [project net PWM.9]
PWRON: J2.5(PWRON) ; port PWRON
SAI.CK: J2.49(SAI_CK) ; port SAI.CK
SAI.D0: J2.53(SAI_D0) ; port SAI.D0
SAI.D1: J2.55(SAI_D1) ; port SAI.D1
SAI.FS: J2.51(SAI_FS) ; port SAI.FS
SCL0: J1.46(I2C0_SCL) ; port I2C0.SCL  [project net I2C0.SCL]
SCL2: J2.47(I2C2_SCL) ; port I2C2.SCL  [project net I2C2.SCL]
SDA0: J1.44(I2C0_SDA) ; port I2C0.SDA  [project net I2C0.SDA]
SDA2: J2.45(I2C2_SDA) ; port I2C2.SDA  [project net I2C2.SDA]
SDC.CD: J1.67(SDC_CD) ; port SDC.CD
SDC.CLK: J1.55(SDC_CLK) ; port SDC.CLK
SDC.CMD: J1.57(SDC_CMD) ; port SDC.CMD
SDC.D0: J1.59(SDC_D0) ; port SDC.D0
SDC.D1: J1.61(SDC_D1) ; port SDC.D1
SDC.D2: J1.63(SDC_D2) ; port SDC.D2
SDC.D3: J1.65(SDC_D3) ; port SDC.D3
SDC.RST: J1.71(SDC_RST) ; port SDC.RST
SDC.WP: J1.69(SDC_WP) ; port SDC.WP
SPDIF.RX: J1.76(SPDIF_RX) ; port SPDIF.RX
SPDIF.TX: J1.74(SPDIF_TX) ; port SPDIF.TX
SPI0.CIPO: J2.39(SPI0_MISO) ; port SPI0.CIPO
SPI0.CK: J2.37(SPI0_CK) ; port SPI0.CK
SPI0.COPI: J2.41(SPI0_MOSI) ; port SPI0.COPI
SPI0.CS: J2.35(SPI0_CS) ; port SPI0.CS
SPI1.CS: J2.36(SPI1_CS) ; port SPI1.CS
TCK/SWCLK: J1.77(JTAG_TCK/SCK) ; port JTAG.TCK/SCK  [project net JTAG.TCK/SCK]
TDI: J1.78(JTAG_TDI) ; port JTAG.TDI  [project net JTAG.TDI]
TDO/SWO: J1.79(JTAG_TDO/SWO) ; port JTAG.TDO/SWO  [project net JTAG.TDO/SWO]
TMS/SWDIO: J1.75(JTAG_TMS/SWD) ; port JTAG.TMS/SWD  [project net JTAG.TMS/SWD]
TRST: J1.80(JTAG_TRST) ; port JTAG.TRST  [project net JTAG.TRST]
UART0_CTS: J1.40(SERIAL0_CTS) ; port UART0.CTS  [project net UART0.CTS]
UART0_RTS: J1.38(SERIAL0_RTS) ; port UART0.RTS  [project net UART0.RTS]
UART0_RX: J1.36(SERIAL0_RX) ; port UART0.RX  [project net UART0.RX]
UART0_TX: J1.34(SERIAL0_TX) ; port UART0.TX  [project net UART0.TX]
UART1_CTS: J1.39(SERIAL1_CTS) ; port UART1.CTS  [project net UART1.CTS]
UART1_RTS: J1.37(SERIAL1_RTS) ; port UART1.RTS  [project net UART1.RTS]
UART1_RX: J1.35(SERIAL1_RX) ; port UART1.RX  [project net UART1.RX]
UART1_TX: J1.33(SERIAL1_TX) ; port UART1.TX  [project net UART1.TX]
UART2.CTS: J2.32(SERIAL2_CTS) ; port UART2.CTS
UART2.RTS: J2.30(SERIAL2_RTS) ; port UART2.RTS
UART2.RX: J2.28(SERIAL2_RX) ; port UART2.RX
UART2.TX: J2.26(SERIAL2_TX) ; port UART2.TX
UART3_CTS: J2.31(SERIAL3_CTS) ; port UART3.CTS  [project net UART3.CTS]
UART3_RTS: J2.29(SERIAL3_RTS) ; port UART3.RTS  [project net UART3.RTS]
UART3_RX: J2.27(SERIAL3_RX) ; port UART3.RX  [project net UART3.RX]
UART3_TX: J2.25(SERIAL3_TX) ; port UART3.TX  [project net UART3.TX]
USB0_D_N: J1.28(USB0_D_N) ; port USB_FS.D_N  [project net USB_FS.D_N]
USB0_D_P: J1.26(USB0_D_P) ; port USB_FS.D_P  [project net USB_FS.D_P]
USB0_ID: J1.30(USB0_ID) ; port USB_FS.ID  [project net USB_FS.ID]
USB0_VBUS: J1.24(USB0_VBUS) ; port USB_FS.VBUS  [project net USB_FS.VBUS]
USB_HS.ID: J1.29(USB1_ID) ; port USB_HS.ID
USB_HS.VBUS: J1.23(USB1_VBUS) ; port USB_HS.VBUS
VSYS: J1.53(VSYS) J1.64(VSYS) ; port VSYS

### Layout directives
differential pair; differential pair class ETH: ETH_A_N, ETH_A_P, ETH_B_N, ETH_B_P, ETH_C_N, ETH_C_P, ETH_D_N, ETH_D_P
differential pair; differential pair class USB: USB_FS.D_N, USB_FS.D_P, USB_HS.D_N, USB_HS.D_P
differential pair; differential pair class DSI: DSI_CK_N, DSI_CK_P, DSI_D0_N, DSI_D0_P, DSI_D1_N, DSI_D1_P, DSI_D2_N, DSI_D2_P, DSI_D3_N, DSI_D3_P
differential pair; differential pair class CAM: CAM_D0_N, CAM_D0_P, CAM_D1_N, CAM_D1_P, CAM_D2_N, CAM_D2_P, CAM_D3_N, CAM_D3_P

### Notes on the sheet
- USB
- Portenta
- J1
- SIDE
- view
- J2
- Carrier
- COLOR LEGEND:
- 1
- 80
- RED WIRES with bold names represent pins shared between two different peripherals/busses on Portenta H7
- BOTTOM
- TOP
- (near PortentaBoardShape_3D_Hirose3.5mm) HD Connectors on the shield are mirrored
- Orange Wires represent not-connected pins on Portenta H7
- TRST vs RESET
- SHARED PINS TABLE (RED WIRES)
- NET
- BUS 1
- BUS 2
- POWER NETS TABLE
- TYPE
- RANGES
- DESCRIPTION
- JTAG
- CAM
- CAM   D3_N
- SDC2
- I2C4
- SAI2A
- PORTENTA INPUT
- PORTENTA OUTPUT
- 4.1V to 6V.
- 1.1V to 3.3V in steps, max 1A.
- RESERVED, DO NOT USE
- Default 3.3V, PMIC (U10) programmable output.
- ANALOG (A4)
- ANALOG (A5)
- CAM   D3_P
- ANALOG
- SPI2 (D10/MISO)
- SPI2 (D8/MOSI)
- PORTENTA RESERVED OUTPUT
- Coinc cell max 3.6V, max 46uA.
- 3.5V to 4.2V, max 600mA.
- Default  4.2V, PMIC (U10) programmable output which is also the input voltage of the bucks inside the PMIC itself.
- Max 4uA with PMIC (U10) in coin cell mode, max 46uA with PMIC in standby/suspend mode.
- Labels drawn without touching a wire or pin: PA4, PA6, PB3, PC2, PC3, PH11, PH12, PI5, PI6, PI7

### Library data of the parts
J1 = J0016-A.10: CONN RCPT FEMALE D80POS 0.4MM SMD GOLD; Manufacturer: Hirose; Number of Contacts: 80; Current Rating: 300mA; Voltage Rating: 30V; Stack Height: 3.5mm; Code Arduino: J0016; Gender: Receptacle; Pitch: 0.016inch
J2 = J0153-A.2: CONN RCPT FEMALE D80POS 0.4MM SMD GOLD; Manufacturer: Hirose; Number of Contacts: 80; Current Rating: 300mA; Voltage Rating: 30V; Stack Height: 3.5mm; Code Arduino: J0016; Gender: Receptacle; Pitch: 0.016inch
PortentaBoardShape_3D_Hirose3.5mm = UT0026-A.2

## Sheet ETHERNET.SchDoc: Portenta Breakout Carrier
size A4; Author: Ernesto Lopez; DocumentNumber: ASX00031; Revision: V1.3; SheetNumber: 3; SheetTotal: 6; RevAuthor: Silvio Navaretti
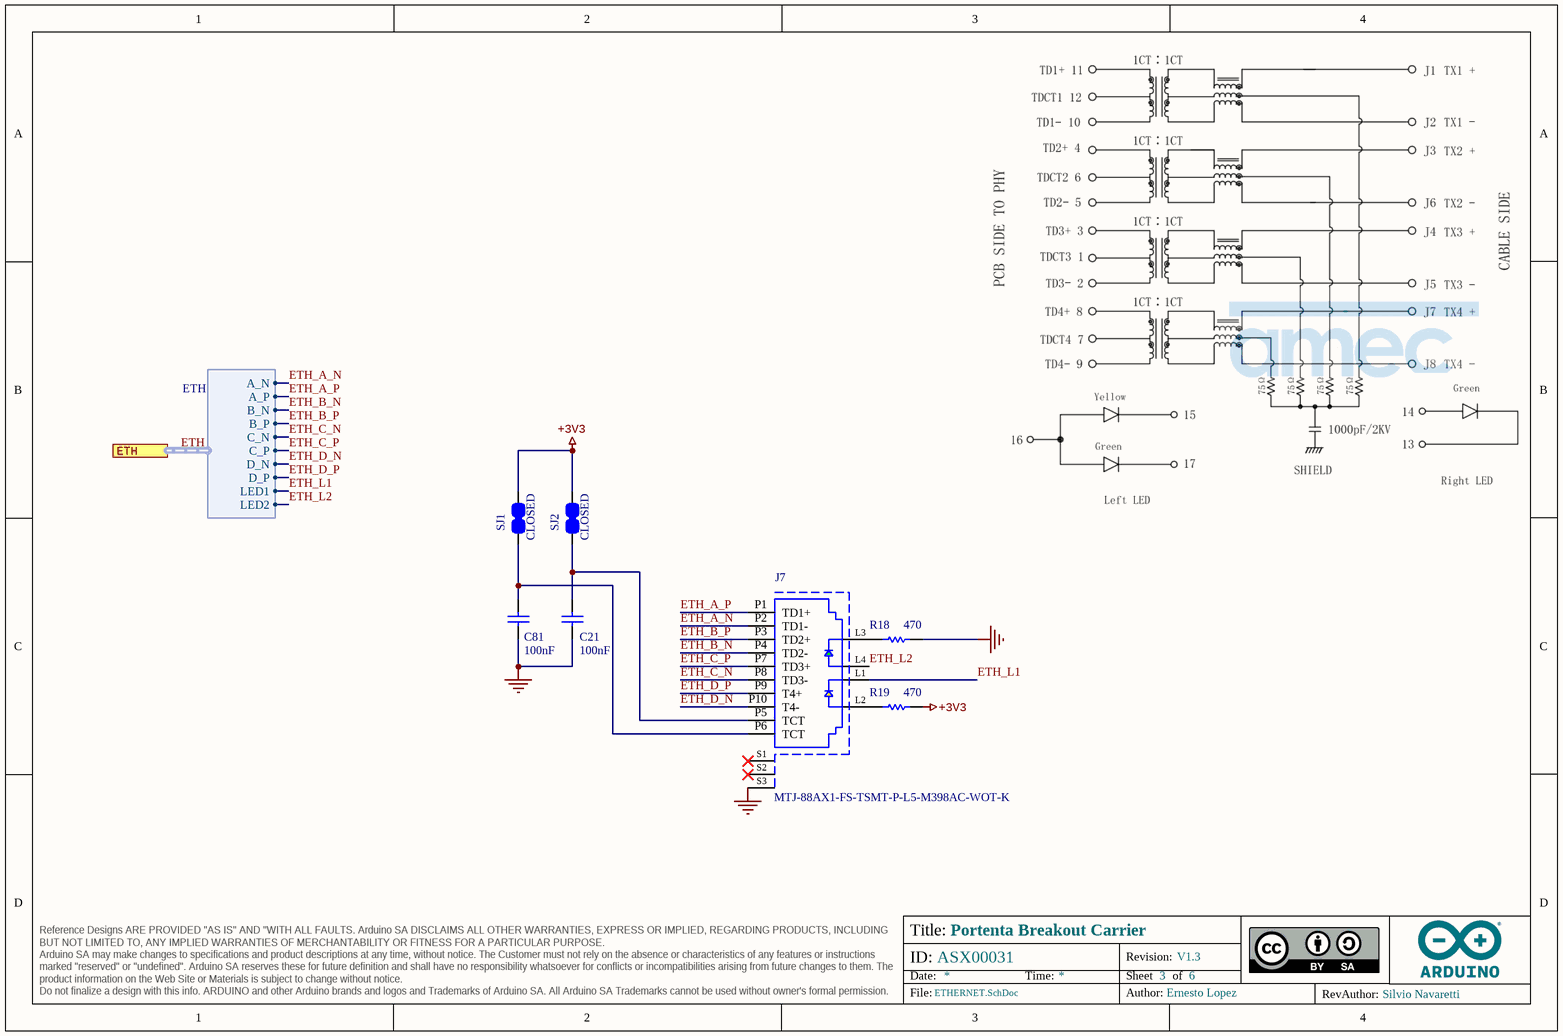
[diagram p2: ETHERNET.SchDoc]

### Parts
C21  value 100nF  [CAP-0402]  (hidden comment: C0402C104K3PACTU)
C81  value 100nF  [CAP-0402]  (hidden comment: C0402C104K3PACTU)
J7  MTJ-88AX1-FS-TSMT-P-L5-M398AC-WOT-K  [MTJ-88AX1-FS-TSMT-P-L5-M398AC-WOT-K-Footprint-1]
R18  value 470  [RES-0402]  (hidden comment: CRCW0402470RJNED)
R19  value 470  [RES-0402]  (hidden comment: CRCW0402470RJNED)
SJ1  SMD solder JUMPER CLOSED  [SJ]  (value not drawn)  (net tie, no BOM)
SJ2  SMD solder JUMPER CLOSED  [SJ]  (value not drawn)  (net tie, no BOM)

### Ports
ETH (harness ETH)

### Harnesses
ETH: A_N, A_P, B_N, B_P, C_N, C_P, D_N, D_P, LED1, LED2

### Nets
+3V3: R19.2 SJ1.2 SJ2.2
GND: C21.2 C81.2 J7.S3(Shield) R18.2
ETH_A_N: J7.P2(TD1-) ; port ETH.A_N  [project net ETH.A_N]
ETH_A_P: J7.P1(TD1+) ; port ETH.A_P  [project net ETH.A_P]
ETH_B_N: J7.P4(TD2-) ; port ETH.B_N  [project net ETH.B_N]
ETH_B_P: J7.P3(TD2+) ; port ETH.B_P  [project net ETH.B_P]
ETH_C_N: J7.P8(TD3-) ; port ETH.C_N  [project net ETH.C_N]
ETH_C_P: J7.P7(TD3+) ; port ETH.C_P  [project net ETH.C_P]
ETH_D_N: J7.P10(T4-) ; port ETH.D_N  [project net ETH.D_N]
ETH_D_P: J7.P9(T4+) ; port ETH.D_P  [project net ETH.D_P]
ETH_L1: J7.L1 ; port ETH.LED1  [project net ETH.LED1]
ETH_L2: J7.L4 ; port ETH.LED2  [project net ETH.LED2]
NetC21_1: C21.1 J7.P5(TCT) SJ2.1
NetC81_1: C81.1 J7.P6(TCT) SJ1.1
NetJ7_L2: J7.L2 R19.1
NetJ7_L3: J7.L3 R18.1

Not connected (* = marked no-connect by the designer): J7 S1(Shield)* S2(Shield)*

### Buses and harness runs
harness ETH = port ETH

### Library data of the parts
C21 C81 = C0014-A.9: CAP CHIP 0402 100nF 25V X5R 10%; Manufacturer: KEMET; Code Arduino: 0132
J7 = J0133-A.6: CONN ETHERNET 1GIGABIT VERTICAL; Manufacturer: Adam Tech; Code Arduino: J0133
R18 R19 = R0055-A.6: RES CHIP 0402 470R 5% 1/16W; Manufacturer: Vishay; Power: 63mW; Code Arduino: R0055; Tolerance: 1%
SJ1 SJ2 = UT0006-A.10: Solder Jumper shorted pads

## Sheet USB.SchDoc: Portenta Breakout Carrier
size A4; Author: Ernesto Lopez; DocumentNumber: ASX00031; Revision: V1.3; SheetNumber: 4; SheetTotal: 6; RevAuthor: Silvio Navaretti
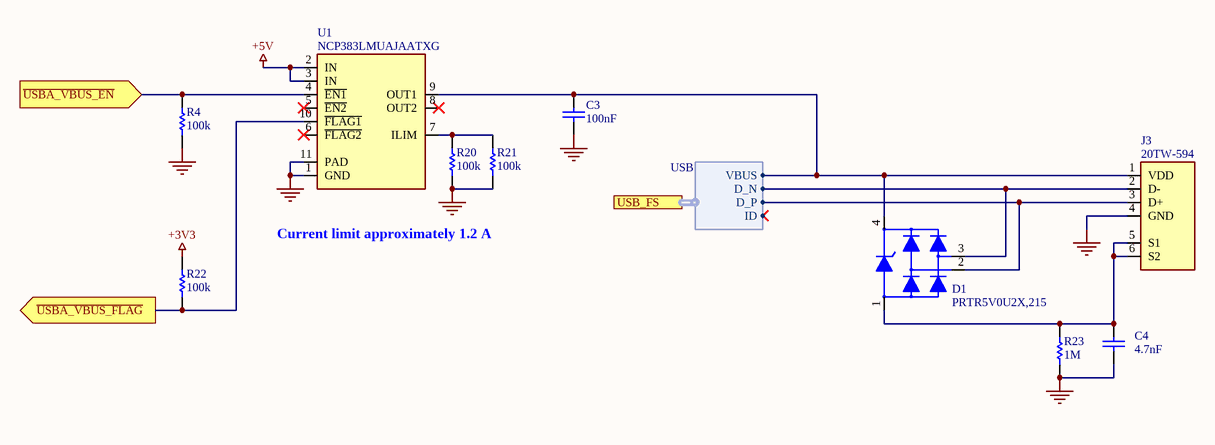
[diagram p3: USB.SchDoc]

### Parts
C3  value 100nF  [CAP-0402]  (hidden comment: C0402C104K3PACTU)
C4  value 4.7nF  [CAP-0805]  (hidden comment: C0805C472KDRACTU)
D1  PRTR5V0U2X,215  [SOT190P230X110-4N]
J3  20TW-594  [20TW595-Footprint-1]
R4  value 100k  [RES-0402]  (hidden comment: CRCW0402100KFKEDC)
R20  value 100k  [RES-0402]  (hidden comment: CRCW0402100KFKEDC)
R21  value 100k  [RES-0402]  (hidden comment: CRCW0402100KFKEDC)
R22  value 100k  [RES-0402]  (hidden comment: CRCW0402100KFKEDC)
R23  value 1M  [RES-0402]  (hidden comment: CRCW04021M00FKED)
U1  NCP383LMUAJAATXG  [PQFN50P300X300X55_HS-21L]

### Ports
USB_FS (harness USB), ~{USBA_VBUS_EN} (in), ~{USBA_VBUS_FLAG} (out)

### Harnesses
USB: VBUS, D_N, D_P, ID

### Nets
+3V3: R22.1
+5V: U1.2(IN) U1.3(IN)
GND: C3.2 C4.1 J3.4(GND) R4.2 R20.2 R21.2 R23.1 U1.1(GND) U1.11(PAD)
~{USBA_VBUS_EN}: R4.1 U1.4(~{EN1}) ; port ~{USBA_VBUS_EN}
~{USBA_VBUS_FLAG}: R22.2 U1.10(~{FLAG1}) ; port ~{USBA_VBUS_FLAG}
USB_FS.D_N: D1.3 J3.2(D-) ; port USB_FS.D_N
USB_FS.D_P: D1.2 J3.3(D+) ; port USB_FS.D_P
USB_FS.VBUS: C3.1 D1.4 J3.1(VDD) U1.9(OUT1) ; port USB_FS.VBUS
NetC4_2: C4.2 D1.1 J3.5(S1) J3.6(S2) R23.2
NetR20_1: R20.1 R21.1 U1.7(ILIM)

Not connected (* = marked no-connect by the designer): U1 5(~{EN2})* 6(~{FLAG2})* 8(OUT2)*

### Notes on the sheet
- Current limit approximately 1.2 A

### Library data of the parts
C3 = C0014-A.9: as C21 on sheet ETHERNET
C4 = C0059-A.9: CAP CHIP 0805 4.7nF 1000V X7R 10%; Manufacturer: KEMET; Voltage: 1kV; Code Arduino: 0689
D1 = D0025-A.3: TVS ARRAY 4LIN.8kV 1pF SOT143B; Manufacturer: Nexperia; Device Type: ESD protection; Code Arduino: 2209
J3 = J0135-A.4: CONN USB A VERTICAL; Manufacturer: 4UCON; Code Arduino: J0135
R4 R20-R22 = R0001-A.5: RES CHIP 0402 100K 1% 1/16W; Manufacturer: Vishay; Power: 63mW; Code Arduino: 0134
R23 = R0058-A.5: RES CHIP 0402 1M 1% 1/16W; Manufacturer: Vishay; Power: 63mW; Code Arduino: 0139
U1 = U0052-A.5: IC POWER SWITCH DUAL CHANNEL OCP; Manufacturer: ON Semiconductor; Max Input Voltage: 5.5V; Min Input Voltage: 2.7V; Turn-Off Delay Time: 3ms; Number of Outputs: 2; Output Configuration: High Side; Turn-On Delay Time: 9ms; Interface: On/Off; Max Power Dissipation: 850mW; Code Arduino: U0052; On-State Resistance: 95mR; Max Output Current: 2.5A; Device Type: PWR SWITCH; Fault Protection: Over Temperature; Max Supply Current: 1uA

## Sheet SD_CONNECTOR.SchDoc: Portenta Breakout Carrier
size A4; Author: Ernesto Lopez; DocumentNumber: ASX00031; Revision: V1.3; SheetNumber: 5; SheetTotal: 6; RevAuthor: Silvio Navaretti
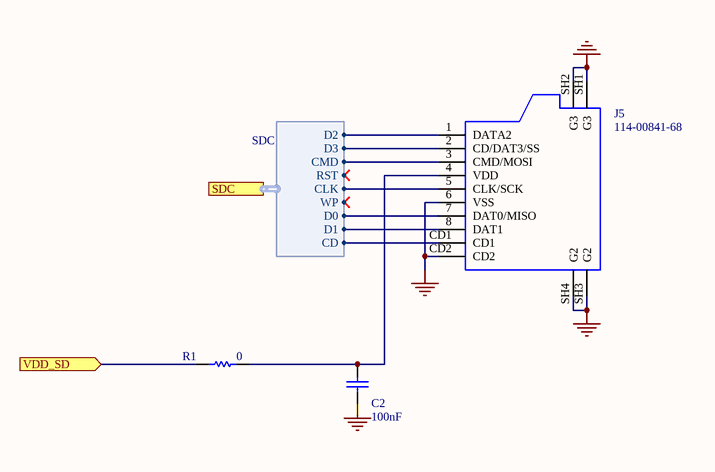
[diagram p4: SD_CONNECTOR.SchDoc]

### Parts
C2  value 100nF  [CAP-0402]  (hidden comment: C0402C104K3PACTU)
J5  114-00841-68  [AMPHENOL_114-00841-68]
R1  value 0  [RES-0402]  (hidden comment: CRCW04020000Z0EDC)

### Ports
SDC (harness SDC), VDD_SD (in)

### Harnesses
SDC: D0, D1, D2, D3, CMD, CLK, CD, WP, RST

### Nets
GND: C2.1 J5.6(VSS) J5.CD2 J5.SH1(G3) J5.SH2(G3) J5.SH3(G2) J5.SH4(G2)
VSD: R1.1 ; port VDD_SD
SDC.CD: J5.CD1 ; port SDC.CD
SDC.CLK: J5.5(CLK/SCK) ; port SDC.CLK
SDC.CMD: J5.3(CMD/MOSI) ; port SDC.CMD
SDC.D0: J5.7(DAT0/MISO) ; port SDC.D0
SDC.D1: J5.8(DAT1) ; port SDC.D1
SDC.D2: J5.1(DATA2) ; port SDC.D2
SDC.D3: J5.2(CD/DAT3/SS) ; port SDC.D3
NetC2_2: C2.2 J5.4(VDD) R1.2

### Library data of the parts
C2 = C0014-A.9: as C21 on sheet ETHERNET
J5 = J0011-A.3: CONN Micro SD; Manufacturer: Amphenol; Code Arduino: A5328
R1 = R0000-A.5: as R5 on sheet TOP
